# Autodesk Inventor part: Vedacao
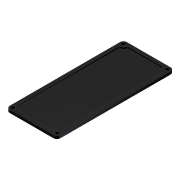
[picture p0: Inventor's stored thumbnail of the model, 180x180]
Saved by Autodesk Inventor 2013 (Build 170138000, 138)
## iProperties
Created: 2010-06
Part Number: Vedacao
Document SubType Name: Modeling
Designer: Usuario
Density: 2.18 g/cm^3
Material: Vidro
Mass: 24.3609 g
Surface Area: 164.43 cm^2
Volume: 11.1747 cm^3
Author: Usuario
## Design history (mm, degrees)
sketch "Sketch1"
  geometry: L1 (-17.35, 59.237)-(17.35, 59.237) reference; L2 (22.237, 54.35)-(22.237, -54.35) reference; L3 (17.35, -59.237)-(-17.35, -59.237) reference; L4 (-22.237, -54.35)-(-22.237, 54.35) reference; L5 (24.5, 65)-(-24.5, 65) reference; L6 (-28, 61.5)-(-28, -61.5) reference; L7 (-24.5, -65)-(24.5, -65) reference; L8 (28, -61.5)-(28, 61.5) reference; C1 r 2 at (-24.5, 61.5) reference; C2 r 2 at (24.5, 61.5) reference; C3 r 2 at (24.5, -61.5) reference; C4 r 2 at (-24.5, -61.5) reference; A1 r 7.5 centre (24.5, 61.5) between (17.35, 59.237) and (22.237, 54.35) reference; A2 r 7.5 centre (24.5, -61.5) between (22.237, -54.35) and (17.35, -59.237) reference; A3 r 7.5 centre (-24.5, -61.5) between (-17.35, -59.237) and (-22.237, -54.35) reference; A4 r 7.5 centre (-24.5, 61.5) between (-22.237, 54.35) and (-17.35, 59.237) reference; A5 r 3.5 centre (24.5, 61.5) between (28, 61.5) and (24.5, 65) reference; A6 r 3.5 centre (-24.5, 61.5) between (-24.5, 65) and (-28, 61.5) reference; A7 r 3.5 centre (-24.5, -61.5) between (-28, -61.5) and (-24.5, -65) reference; A8 r 3.5 centre (24.5, -61.5) between (24.5, -65) and (28, -61.5) reference; 1 further point
extrude "Extrusion1" new body sketch "Sketch1" distance "d0" = 3.2; taper "d1" = 0 deg
sketch "Sketch2"
  geometry: L1 (-20, 61.5)-(20, 61.5) reference; L2 (-24.5, -57)-(-24.5, 57) reference; L3 (24.5, 57)-(24.5, -57) reference; L4 (20, -61.5)-(-20, -61.5) reference; A1 r 4.5 centre (-24.5, 61.5) between (-24.5, 57) and (-20, 61.5) reference; A2 r 4.5 centre (24.5, 61.5) between (20, 61.5) and (24.5, 57) reference; A3 r 4.5 centre (24.5, -61.5) between (24.5, -57) and (20, -61.5) reference; A4 r 4.5 centre (-24.5, -61.5) between (-20, -61.5) and (-24.5, -57) reference; 1 further point
extrude "Extrusion2" cut sketch "Sketch2" distance "d2" = 2; taper "d3" = 0 deg
body "Solid1"
node "Reference1"
node "Reference2"
node "Reference3"
node "Reference4"
node "Reference5"
node "Reference6"
node "Reference7"
node "Reference8"
node "Reference9"
